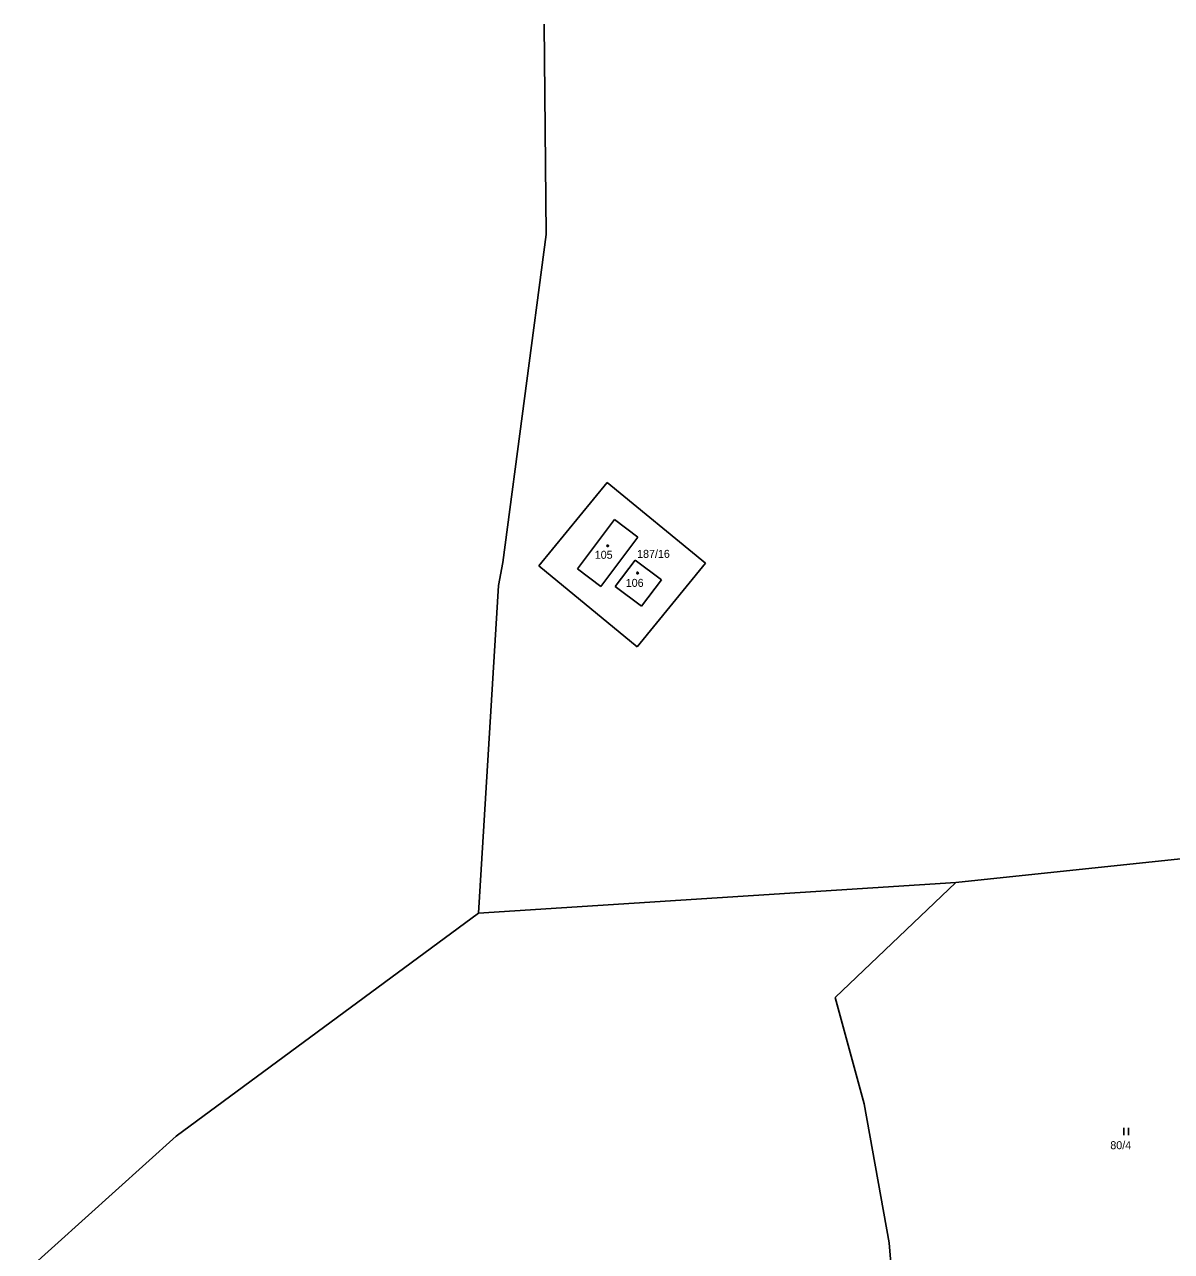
# Model space of a CAD drawing. Extents: x -811039 to -805820, y -1161436 to -1155864.
# Drawn here: x -807015.3 to -806771.7, y -1157988.2 to -1157727.6 of the extents above; entities that cross this region are included whole.
import ezdxf

# ---------------------------------------------------------------- set-up
doc = ezdxf.new("R2010")
doc.units = 0
for name, color, linetype in [('Default', 7, 'Continuous'), ('KN_HRANICE', 7, 'Continuous'), ('KN_KULTURY', 7, 'Continuous'), ('KN_PARCELY', 7, 'Continuous')]:
    doc.layers.add(name, color=color, linetype=linetype)

# ---------------------------------------------------------------- blocks, each defined once
blk = doc.blocks.new('306')
at = {"layer": 'Default'}
for p, q in [((-0.5, 1.5), (-0.5, 0)), ((0.5, 0), (0.5, 1.5))]:
    blk.add_line(p, q, dxfattribs=at)
blk = doc.blocks.new('402')
at = {"layer": 'Default'}
blk.add_lwpolyline([(0.09, 0.15), (0.18, 0), (0.09, -0.15), (-0.09, -0.15), (-0.18, 0), (-0.09, 0.15), (0.09, 0.15)], dxfattribs=at)

msp = doc.modelspace()

# ---------------------------------------------------------------- linework, layer by layer
at = {"layer": 'KN_HRANICE'}
for p, q in [((-806904.94, -1157727.56), (-806904.51, -1157772.27)), ((-806904.94, -1157727.56), (-806904.51, -1157772.27)), ((-806904.51, -1157772.27), (-806913.67, -1157841.92)), ((-806904.51, -1157772.27), (-806913.67, -1157841.92)), ((-806906.04, -1157842.65), (-806891.54, -1157824.95)), ((-806891.54, -1157824.95), (-806870.67, -1157842.05)), ((-806897.86, -1157843.25), (-806890, -1157832.76)), ((-806890, -1157832.76), (-806884.99, -1157836.53)), ((-806884.99, -1157836.53), (-806892.84, -1157847)), ((-806914.59, -1157846.83), (-806913.67, -1157841.92)), ((-806914.59, -1157846.83), (-806913.67, -1157841.92)), ((-806885.18, -1157859.86), (-806906.04, -1157842.65)), ((-806889.8, -1157847), (-806885.58, -1157841.39)), ((-806885.58, -1157841.39), (-806879.99, -1157845.59)), ((-806870.67, -1157842.05), (-806885.18, -1157859.86)), ((-806892.84, -1157847), (-806897.86, -1157843.25)), ((-806879.99, -1157845.59), (-806884.21, -1157851.19)), ((-806918.82, -1157916.41), (-806914.59, -1157846.83)), ((-806918.82, -1157916.41), (-806914.59, -1157846.83)), ((-806884.21, -1157851.19), (-806889.8, -1157847)), ((-806817.49, -1157909.9), (-806760.28, -1157903.83)), ((-806817.49, -1157909.9), (-806918.82, -1157916.41)), ((-806843.07, -1157934.32), (-806817.49, -1157909.9)), ((-806918.82, -1157916.41), (-806983.04, -1157963.76)), ((-806918.82, -1157916.41), (-806983.04, -1157963.76)), ((-806836.94, -1157956.88), (-806843.07, -1157934.32)), ((-806831.65, -1157986.44), (-806836.94, -1157956.88)), ((-806983.04, -1157963.76), (-807015.26, -1157992.79)), ((-806983.04, -1157963.76), (-807015.26, -1157992.79)), ((-806831.65, -1157986.44), (-806829.24, -1158014.95))]:
    msp.add_line(p, q, dxfattribs=at)

# ---------------------------------------------------------------- block references
at = {"layer": 'KN_KULTURY'}
for name, p in [('402', (-806891.41, -1157838.36)), ('402', (-806885.08, -1157844.14)), ('306', (-806781.28, -1157963.52))]:
    msp.add_blockref(name, p, dxfattribs=at)

# ---------------------------------------------------------------- texts
at = {"layer": 'KN_PARCELY'}
for s, p in [('105', (-806894.16, -1157841.12)), ('187/16', (-806885.17, -1157840.93)), ('106', (-806887.58, -1157847.09)), ('80/4', (-806784.67, -1157966.53))]:
    msp.add_text(s, height=1.7, dxfattribs=at).set_placement(p)

doc.saveas('drawing.dxf')
